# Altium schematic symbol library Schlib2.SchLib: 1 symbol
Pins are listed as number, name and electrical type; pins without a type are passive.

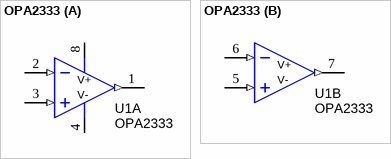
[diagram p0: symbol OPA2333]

## OPA2333
designator U1
Manufacturer: Texas Instruments; Characteristics: 1.8V, High CMR, RRIO Op Amp; CompType: OpAmp IC; Value: LF353M; TaMin_C: 0.0; TaMax_C: 70.0; PowerWise: N
3D model M08A
footprint M08A_L
footprint M08A_M
footprint M08A_N
simulation model LF353 (SUBCKT)
part A pins: 1 OUT (out), 2 IN- (in), 3 IN+ (in), 4 V-, 8 V+
part B pins: 5 IN+ (in), 6 IN- (in), 7 OUT (out)
3 alternate drawings of the same symbol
